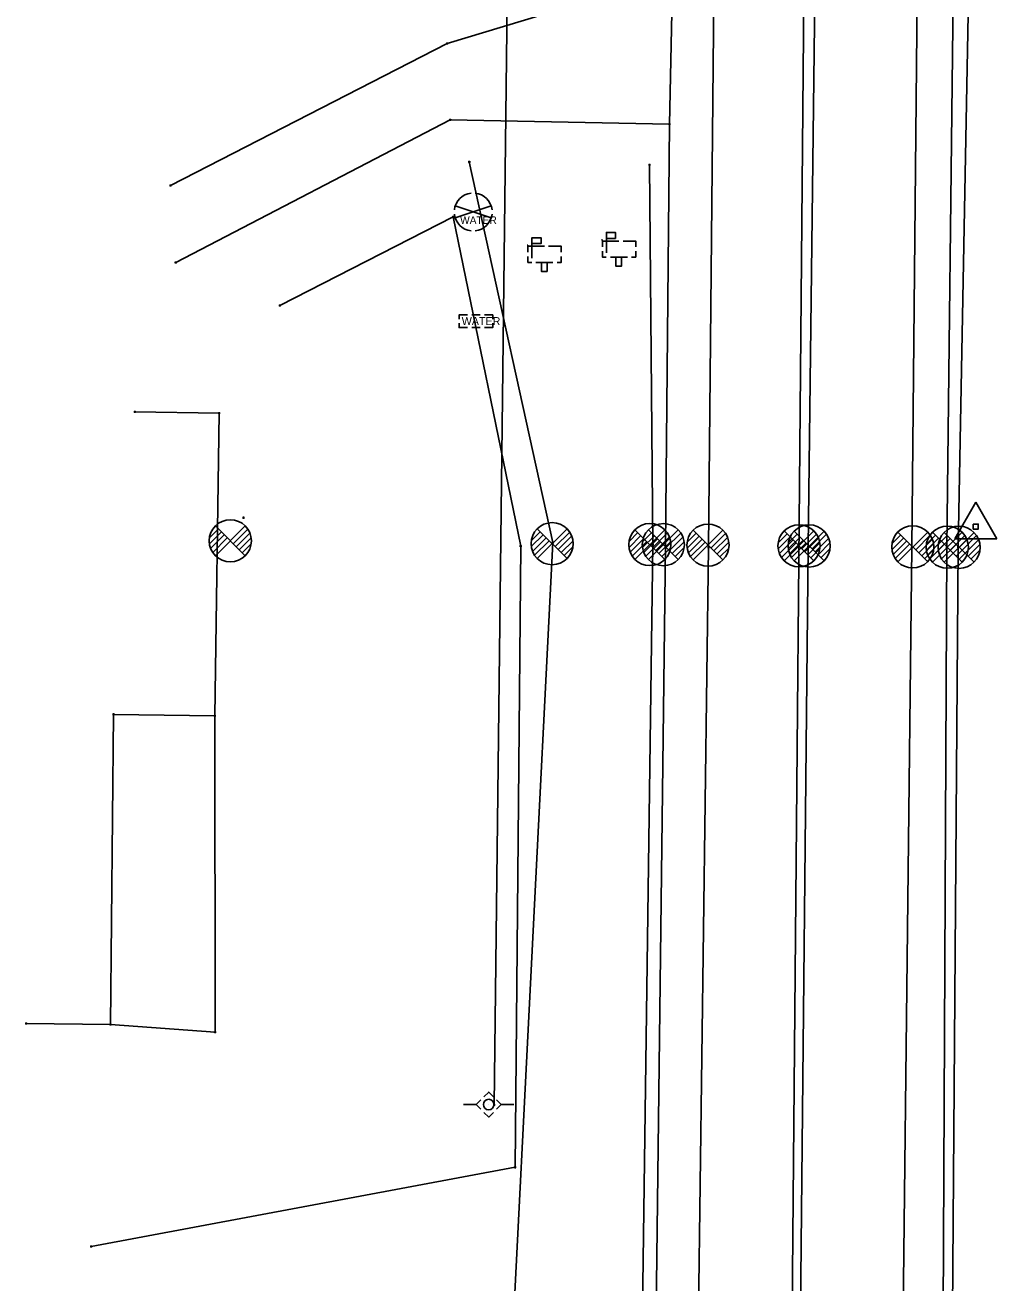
# Model space of a CAD drawing. Extents: x 1954856 to 2011933, y 399149 to 426294.
# Drawn here: x 2003853.9 to 2003969.2, y 411391.5 to 411540.8 of the extents above; entities that cross this region are included whole.
import ezdxf

# ---------------------------------------------------------------- set-up
doc = ezdxf.new("R2010")
doc.units = 0
for name, color, linetype in [('BankMent_ep', 7, 'Continuous'), ('BaselineSurvey', 7, 'Continuous'), ('Building_ep', 7, 'Continuous'), ('Deck_ep', 7, 'Continuous'), ('Driveway_ep', 7, 'Continuous'), ('ElecAer_ep', 7, 'Continuous'), ('Mailbox_ep', 7, 'Continuous'), ('MeterWater_ep', 7, 'Continuous'), ('MonumentNL_ep', 7, 'Continuous'), ('PavtAsphalt_ep', 7, 'Continuous'), ('PavtAsphaltCrown_ep', 7, 'Continuous'), ('PointLocator_ep', 7, 'Continuous'), ('PoleShared_ep', 7, 'Continuous'), ('ShldrPaved_ep', 7, 'Continuous'), ('TreeLineWoods_ep', 7, 'Continuous'), ('ValveCvrWater_ep', 7, 'Continuous'), ('XSPt_ep', 7, 'Continuous')]:
    doc.layers.add(name, color=color, linetype=linetype)

msp = doc.modelspace()

# ---------------------------------------------------------------- linework, layer by layer
at = {"layer": 'BankMent_ep'}
for p, q in [((2003964.59, 411478.82), (2003966.14, 411562.47)), ((2003963.86, 411378.27), (2003964.59, 411478.82))]:
    msp.add_line(p, q, dxfattribs=at)
for points in [[(2003912.38, 411279.6), (2003911.48, 411380.96), (2003916.5, 411479.37), (2003906.57, 411524.55)], [(2003926.31, 411279.68), (2003927.01, 411379.57), (2003928.36, 411479.13), (2003927.97, 411524.18)]]:
    msp.add_lwpolyline(points, dxfattribs=at)
at = {"layer": 'BaselineSurvey'}
msp.add_line((2003939.73, 410808.61), (2003953.03, 412299.6), dxfattribs=at)
msp.add_line((2003939.73, 410808.61), (2003953.03, 412299.6), dxfattribs=at)
at = {"layer": 'Building_ep'}
msp.add_lwpolyline([(2003866.89, 411494.87), (2003876.89, 411494.72), (2003876.35, 411458.79), (2003864.35, 411458.97), (2003863.98, 411422.19), (2003853.98, 411422.29)], dxfattribs=at)
at = {"layer": 'Deck_ep'}
msp.add_lwpolyline([(2003876.35, 411458.79), (2003876.39, 411421.28), (2003863.98, 411422.19)], dxfattribs=at)
at = {"layer": 'Driveway_ep'}
for points in [[(2003871.11, 411521.73), (2003903.94, 411538.58), (2003930.69, 411546.69)], [(2003930.33, 411529), (2003904.31, 411529.53), (2003871.73, 411512.61)]]:
    msp.add_lwpolyline(points, dxfattribs=at)
at = {"layer": 'ElecAer_ep'}
msp.add_lwpolyline([(2003909.52, 411412.64), (2003912.81, 411691.22), (2003877.86, 411706.6)], dxfattribs=at)
at = {"layer": 'Mailbox_ep'}
for p, q in [((2003913.53, 411514.52), (2003913.53, 411513.82)), ((2003915.48, 411514.52), (2003913.53, 411514.52)), ((2003914, 411513.11), (2003914, 411514.84)), ((2003914, 411514.84), (2003914.98, 411514.84)), ((2003917.48, 411514.52), (2003917.48, 411513.82)), ((2003922.37, 411515.14), (2003922.37, 411514.44)), ((2003924.33, 411515.14), (2003922.37, 411515.14)), ((2003922.84, 411513.73), (2003922.84, 411515.46)), ((2003922.84, 411515.46), (2003923.83, 411515.46)), ((2003926.33, 411515.14), (2003926.33, 411514.44)), ((2003917.48, 411513.32), (2003917.48, 411512.61)), ((2003923.33, 411513.23), (2003923.83, 411513.23)), ((2003923.83, 411513.23), (2003925.33, 411513.23)), ((2003926.33, 411513.94), (2003926.33, 411513.23)), ((2003914.48, 411512.61), (2003914.98, 411512.61)), ((2003914.98, 411512.61), (2003916.48, 411512.61)), ((2003915.47, 411511.53), (2003915.47, 411511.53)), ((2003924.31, 411512.16), (2003924.31, 411512.16))]:
    msp.add_line(p, q, dxfattribs=at)
for points in [[(2003923.83, 411516.16), (2003922.84, 411516.16), (2003922.84, 411515.46)], [(2003923.83, 411515.46), (2003923.92, 411515.46), (2003923.92, 411516.16), (2003923.83, 411516.16)], [(2003913.42, 411514.65), (2003913.5, 411514.65), (2003913.53, 411514.48)], [(2003914.98, 411515.53), (2003914, 411515.53), (2003914, 411514.84)], [(2003914.98, 411514.84), (2003915.08, 411514.84), (2003915.08, 411515.53), (2003914.98, 411515.53)], [(2003917.48, 411514.07), (2003917.48, 411514.52), (2003915.98, 411514.52)], [(2003922.26, 411515.27), (2003922.34, 411515.27), (2003922.37, 411515.1)], [(2003926.33, 411514.69), (2003926.33, 411515.14), (2003924.83, 411515.14)], [(2003913.53, 411513.32), (2003913.53, 411512.61), (2003913.98, 411512.61)], [(2003916.98, 411512.61), (2003917.48, 411512.61), (2003917.48, 411513.07)], [(2003922.37, 411513.94), (2003922.37, 411513.23), (2003922.83, 411513.23)], [(2003923.96, 411513.23), (2003923.96, 411512.16), (2003924.65, 411512.16), (2003924.65, 411513.23)], [(2003925.83, 411513.23), (2003926.33, 411513.23), (2003926.33, 411513.69)], [(2003915.12, 411512.61), (2003915.12, 411511.53), (2003915.81, 411511.53), (2003915.81, 411512.61)]]:
    msp.add_lwpolyline(points, dxfattribs=at)
at = {"layer": 'MeterWater_ep'}
msp.add_line((2003907.36, 411505.63), (2003907.36, 411505.63), dxfattribs=at)
for points in [[(2003905.36, 411505.88), (2003905.36, 411506.38), (2003906.36, 411506.38)], [(2003906.86, 411506.38), (2003907.86, 411506.38)], [(2003908.36, 411506.38), (2003909.36, 411506.38), (2003909.36, 411505.88)], [(2003906.36, 411504.88), (2003905.36, 411504.88), (2003905.36, 411505.38)], [(2003907.86, 411504.88), (2003906.86, 411504.88)], [(2003909.36, 411505.38), (2003909.36, 411504.88), (2003908.36, 411504.88)]]:
    msp.add_lwpolyline(points, dxfattribs=at)
at = {"layer": 'MonumentNL_ep'}
for p, q in [((2003964.18, 411479.82), (2003966.68, 411484.15)), ((2003966.68, 411484.15), (2003969.18, 411479.82)), ((2003966.68, 411481.26), (2003966.68, 411481.26)), ((2003964.18, 411479.82), (2003969.18, 411479.82))]:
    msp.add_line(p, q, dxfattribs=at)
msp.add_lwpolyline([(2003966.38, 411481.56), (2003966.98, 411481.56), (2003966.98, 411480.96), (2003966.38, 411480.96)], close=True, dxfattribs=at)
at = {"layer": 'PavtAsphalt_ep'}
for p, q in [((2003934.97, 411478.76), (2003935.91, 411579.3)), ((2003959.08, 411478.78), (2003960.06, 411578.43)), ((2003933.66, 411379.39), (2003934.97, 411478.76)), ((2003957.96, 411378.28), (2003959.08, 411478.78))]:
    msp.add_line(p, q, dxfattribs=at)
at = {"layer": 'PavtAsphaltCrown_ep'}
for p, q in [((2003946.8, 411478.86), (2003947.97, 411578.87)), ((2003945.8, 411378.98), (2003946.8, 411478.86))]:
    msp.add_line(p, q, dxfattribs=at)
at = {"layer": 'PointLocator_ep'}
for p, q in [((2003904.07, 411538.58), (2003903.82, 411538.58)), ((2003903.94, 411538.46), (2003903.94, 411538.71)), ((2003903.94, 411538.58), (2003903.94, 411538.58)), ((2003904.44, 411529.53), (2003904.19, 411529.53)), ((2003904.31, 411529.41), (2003904.31, 411529.66)), ((2003904.31, 411529.53), (2003904.31, 411529.53)), ((2003930.46, 411529), (2003930.21, 411529)), ((2003930.33, 411528.88), (2003930.33, 411529.13)), ((2003930.33, 411529), (2003930.33, 411529)), ((2003906.7, 411524.55), (2003906.45, 411524.55)), ((2003906.57, 411524.42), (2003906.57, 411524.67)), ((2003906.57, 411524.55), (2003906.57, 411524.55)), ((2003928.09, 411524.18), (2003927.84, 411524.18)), ((2003927.97, 411524.06), (2003927.97, 411524.31)), ((2003927.97, 411524.18), (2003927.97, 411524.18)), ((2003871.11, 411521.6), (2003871.11, 411521.85)), ((2003871.23, 411521.73), (2003870.98, 411521.73)), ((2003871.11, 411521.73), (2003871.11, 411521.73)), ((2003904.77, 411518.01), (2003904.52, 411518.01)), ((2003904.64, 411517.88), (2003904.64, 411518.13)), ((2003904.64, 411518.01), (2003904.64, 411518.01)), ((2003871.85, 411512.61), (2003871.6, 411512.61)), ((2003871.73, 411512.48), (2003871.73, 411512.73)), ((2003871.73, 411512.61), (2003871.73, 411512.61)), ((2003884.2, 411507.49), (2003883.95, 411507.49)), ((2003884.07, 411507.37), (2003884.07, 411507.62)), ((2003884.07, 411507.49), (2003884.07, 411507.49)), ((2003866.89, 411494.75), (2003866.89, 411495)), ((2003867.01, 411494.87), (2003866.76, 411494.87)), ((2003866.89, 411494.87), (2003866.89, 411494.87)), ((2003877.01, 411494.72), (2003876.76, 411494.72)), ((2003876.89, 411494.6), (2003876.89, 411494.85)), ((2003876.89, 411494.72), (2003876.89, 411494.72)), ((2003879.9, 411482.31), (2003879.65, 411482.31)), ((2003879.78, 411482.19), (2003879.78, 411482.44)), ((2003879.78, 411482.31), (2003879.78, 411482.31)), ((2003912.79, 411478.95), (2003912.54, 411478.95)), ((2003912.67, 411478.82), (2003912.67, 411479.07)), ((2003912.67, 411478.95), (2003912.67, 411478.95)), ((2003916.62, 411479.37), (2003916.37, 411479.37)), ((2003916.5, 411479.24), (2003916.5, 411479.49)), ((2003916.5, 411479.37), (2003916.5, 411479.37)), ((2003928.49, 411479.13), (2003928.24, 411479.13)), ((2003928.36, 411479), (2003928.36, 411479.25)), ((2003928.36, 411479.13), (2003928.36, 411479.13)), ((2003929.98, 411478.97), (2003929.73, 411478.97)), ((2003929.85, 411478.84), (2003929.85, 411479.09)), ((2003929.85, 411478.97), (2003929.85, 411478.97)), ((2003935.09, 411478.76), (2003934.84, 411478.76)), ((2003934.97, 411478.64), (2003934.97, 411478.89)), ((2003934.97, 411478.76), (2003934.97, 411478.76)), ((2003946.93, 411478.86), (2003946.68, 411478.86)), ((2003946.8, 411478.74), (2003946.8, 411478.99)), ((2003946.8, 411478.86), (2003946.8, 411478.86)), ((2003959.21, 411478.78), (2003958.96, 411478.78)), ((2003959.08, 411478.65), (2003959.08, 411478.9)), ((2003959.08, 411478.78), (2003959.08, 411478.78)), ((2003963.36, 411478.8), (2003963.11, 411478.8)), ((2003963.23, 411478.68), (2003963.23, 411478.93)), ((2003963.23, 411478.8), (2003963.23, 411478.8)), ((2003964.72, 411478.82), (2003964.47, 411478.82)), ((2003964.59, 411478.69), (2003964.59, 411478.94)), ((2003964.59, 411478.82), (2003964.59, 411478.82)), ((2003864.48, 411458.97), (2003864.23, 411458.97)), ((2003864.35, 411458.85), (2003864.35, 411459.1)), ((2003864.35, 411458.97), (2003864.35, 411458.97)), ((2003876.48, 411458.79), (2003876.23, 411458.79)), ((2003876.35, 411458.67), (2003876.35, 411458.92)), ((2003876.35, 411458.79), (2003876.35, 411458.79)), ((2003854.11, 411422.29), (2003853.86, 411422.29)), ((2003853.98, 411422.17), (2003853.98, 411422.42)), ((2003853.98, 411422.29), (2003853.98, 411422.29)), ((2003864.1, 411422.19), (2003863.85, 411422.19)), ((2003863.98, 411422.07), (2003863.98, 411422.32)), ((2003863.98, 411422.19), (2003863.98, 411422.19)), ((2003876.51, 411421.28), (2003876.26, 411421.28)), ((2003876.39, 411421.15), (2003876.39, 411421.4)), ((2003876.39, 411421.28), (2003876.39, 411421.28)), ((2003909.64, 411412.64), (2003909.39, 411412.64)), ((2003909.52, 411412.51), (2003909.52, 411412.76)), ((2003909.52, 411412.64), (2003909.52, 411412.64)), ((2003912.13, 411405.23), (2003911.88, 411405.23)), ((2003912, 411405.1), (2003912, 411405.35)), ((2003912, 411405.23), (2003912, 411405.23)), ((2003861.82, 411395.83), (2003861.57, 411395.83)), ((2003861.7, 411395.7), (2003861.7, 411395.95)), ((2003861.7, 411395.83), (2003861.7, 411395.83))]:
    msp.add_line(p, q, dxfattribs=at)
at = {"layer": 'PoleShared_ep'}
for p, q in [((2003907.38, 411412.67), (2003907.94, 411413.24)), ((2003905.88, 411412.67), (2003907.38, 411412.67)), ((2003907.94, 411412.11), (2003907.38, 411412.67)), ((2003908.87, 411412.67), (2003908.87, 411412.67)), ((2003911.85, 411412.67), (2003910.35, 411412.67))]:
    msp.add_line(p, q, dxfattribs=at)
for points in [[(2003908.3, 411413.6), (2003908.87, 411414.16), (2003909.43, 411413.59)], [(2003909.79, 411413.24), (2003910.35, 411412.67), (2003909.79, 411412.11)], [(2003909.43, 411411.75), (2003908.87, 411411.18), (2003908.3, 411411.75)]]:
    msp.add_lwpolyline(points, dxfattribs=at)
for start, end in [(90, 270), (270, 90)]:
    msp.add_arc((2003908.87, 411412.67), 0.625, start, end, dxfattribs=at)
at = {"layer": 'ShldrPaved_ep'}
for p, q in [((2003963.23, 411478.8), (2003964.4, 411578.36)), ((2003930.33, 411529), (2003930.69, 411546.69)), ((2003929.85, 411478.97), (2003930.33, 411529)), ((2003928.66, 411379.34), (2003929.85, 411478.97)), ((2003962.77, 411378.34), (2003963.23, 411478.8))]:
    msp.add_line(p, q, dxfattribs=at)
at = {"layer": 'TreeLineWoods_ep'}
msp.add_lwpolyline([(2003861.7, 411395.83), (2003912, 411405.23), (2003912.67, 411478.95), (2003904.64, 411518.01), (2003884.07, 411507.49)], dxfattribs=at)
at = {"layer": 'ValveCvrWater_ep'}
for p, q in [((2003904.9, 411517.88), (2003909.17, 411519.3)), ((2003909.17, 411517.88), (2003904.9, 411519.3)), ((2003907.03, 411518.59), (2003907.03, 411518.59))]:
    msp.add_line(p, q, dxfattribs=at)
for start, end in [(96.3794, 173.6206), (6.3794, 83.6206), (186.3794, 263.6206), (276.3794, 353.6206)]:
    msp.add_arc((2003907.03, 411518.59), 2.25, start, end, dxfattribs=at)
at = {"layer": 'XSPt_ep'}
for p, q in [((2003875.73, 411479.92), (2003876.79, 411480.98)), ((2003875.73, 411479.22), (2003877.14, 411480.63)), ((2003875.87, 411478.66), (2003877.49, 411480.28)), ((2003876.43, 411477.8), (2003879.97, 411481.34)), ((2003879.97, 411477.8), (2003876.43, 411481.34)), ((2003878.56, 411479.22), (2003880.29, 411480.95)), ((2003878.91, 411478.86), (2003880.53, 411480.48)), ((2003913.93, 411479.58), (2003914.99, 411480.64)), ((2003913.93, 411478.88), (2003915.34, 411480.29)), ((2003914.63, 411477.46), (2003918.17, 411481)), ((2003918.17, 411477.46), (2003914.63, 411481)), ((2003916.75, 411478.88), (2003918.49, 411480.61)), ((2003917.11, 411478.52), (2003918.73, 411480.14)), ((2003925.53, 411479.48), (2003926.59, 411480.54)), ((2003925.53, 411478.77), (2003926.94, 411480.19)), ((2003926.23, 411477.36), (2003929.77, 411480.89)), ((2003929.77, 411477.36), (2003926.23, 411480.89)), ((2003927.13, 411479.46), (2003928.19, 411480.53)), ((2003927.13, 411478.76), (2003928.54, 411480.17)), ((2003927.83, 411477.34), (2003931.37, 411480.88)), ((2003931.37, 411477.34), (2003927.83, 411480.88)), ((2003928.35, 411478.77), (2003930.09, 411480.5)), ((2003929.95, 411478.76), (2003931.69, 411480.49)), ((2003932.43, 411479.42), (2003933.49, 411480.48)), ((2003932.43, 411478.71), (2003933.84, 411480.12)), ((2003933.13, 411477.3), (2003936.67, 411480.83)), ((2003936.67, 411477.3), (2003933.13, 411480.83)), ((2003935.25, 411478.71), (2003936.99, 411480.44)), ((2003943.23, 411479.32), (2003944.29, 411480.38)), ((2003943.93, 411477.2), (2003947.47, 411480.74)), ((2003947.47, 411477.2), (2003943.93, 411480.74)), ((2003944.42, 411479.31), (2003945.48, 411480.37)), ((2003945.13, 411477.19), (2003948.67, 411480.72)), ((2003948.67, 411477.19), (2003945.13, 411480.72)), ((2003946.05, 411478.61), (2003947.79, 411480.35)), ((2003947.25, 411478.6), (2003948.98, 411480.34)), ((2003956.72, 411479.2), (2003957.78, 411480.26)), ((2003957.43, 411477.08), (2003960.97, 411480.61)), ((2003960.97, 411477.08), (2003957.43, 411480.61)), ((2003959.55, 411478.49), (2003961.28, 411480.23)), ((2003960.82, 411479.16), (2003961.88, 411480.23)), ((2003961.53, 411477.04), (2003965.07, 411480.58)), ((2003965.07, 411477.04), (2003961.53, 411480.58)), ((2003962.22, 411479.15), (2003963.28, 411480.21)), ((2003962.93, 411477.03), (2003966.47, 411480.57)), ((2003966.47, 411477.03), (2003962.93, 411480.57)), ((2003963.65, 411478.46), (2003965.38, 411480.19)), ((2003965.05, 411478.44), (2003966.78, 411480.18)), ((2003876.12, 411478.19), (2003877.85, 411479.92)), ((2003878.2, 411479.57), (2003878.2, 411479.57)), ((2003879.26, 411478.51), (2003880.68, 411479.92)), ((2003879.62, 411478.15), (2003880.68, 411479.22)), ((2003914.07, 411478.32), (2003915.69, 411479.94)), ((2003914.32, 411477.85), (2003916.05, 411479.58)), ((2003916.4, 411479.23), (2003916.4, 411479.23)), ((2003917.46, 411478.17), (2003918.88, 411479.58)), ((2003917.82, 411477.81), (2003918.88, 411478.88)), ((2003925.67, 411478.21), (2003927.29, 411479.83)), ((2003925.91, 411477.75), (2003927.65, 411479.48)), ((2003927.27, 411478.2), (2003928.89, 411479.82)), ((2003927.51, 411477.73), (2003929.25, 411479.46)), ((2003928, 411479.12), (2003928, 411479.12)), ((2003928.71, 411478.42), (2003930.33, 411480.04)), ((2003929.06, 411478.06), (2003930.47, 411479.48)), ((2003929.41, 411477.71), (2003930.47, 411478.77)), ((2003929.6, 411479.11), (2003929.6, 411479.11)), ((2003930.31, 411478.4), (2003931.93, 411480.02)), ((2003930.66, 411478.05), (2003932.07, 411479.46)), ((2003931.01, 411477.7), (2003932.07, 411478.76)), ((2003932.57, 411478.15), (2003934.19, 411479.77)), ((2003932.81, 411477.69), (2003934.55, 411479.42)), ((2003934.9, 411479.06), (2003934.9, 411479.06)), ((2003935.61, 411478.36), (2003937.23, 411479.98)), ((2003935.96, 411478), (2003937.37, 411479.42)), ((2003936.31, 411477.65), (2003937.37, 411478.71)), ((2003943.23, 411478.61), (2003944.64, 411480.03)), ((2003943.37, 411478.05), (2003944.99, 411479.68)), ((2003943.61, 411477.59), (2003945.35, 411479.32)), ((2003944.42, 411478.6), (2003945.84, 411480.02)), ((2003944.57, 411478.04), (2003946.19, 411479.66)), ((2003944.81, 411477.58), (2003946.55, 411479.31)), ((2003945.7, 411478.97), (2003945.7, 411478.97)), ((2003946.41, 411478.26), (2003948.03, 411479.88)), ((2003946.76, 411477.91), (2003948.17, 411479.32)), ((2003946.9, 411478.96), (2003946.9, 411478.96)), ((2003947.11, 411477.55), (2003948.17, 411478.61)), ((2003947.61, 411478.25), (2003949.23, 411479.87)), ((2003947.96, 411477.9), (2003949.37, 411479.31)), ((2003948.31, 411477.54), (2003949.37, 411478.6)), ((2003956.72, 411478.49), (2003958.14, 411479.91)), ((2003956.87, 411477.93), (2003958.49, 411479.55)), ((2003957.11, 411477.47), (2003958.85, 411479.2)), ((2003959.2, 411478.85), (2003959.2, 411478.85)), ((2003959.91, 411478.14), (2003961.53, 411479.76)), ((2003960.26, 411477.79), (2003961.67, 411479.2)), ((2003960.82, 411478.46), (2003962.24, 411479.87)), ((2003960.97, 411477.9), (2003962.59, 411479.52)), ((2003961.21, 411477.43), (2003962.95, 411479.16)), ((2003962.22, 411478.44), (2003963.64, 411479.86)), ((2003962.37, 411477.88), (2003963.99, 411479.51)), ((2003962.61, 411477.42), (2003964.35, 411479.15)), ((2003963.3, 411478.81), (2003963.3, 411478.81)), ((2003964.01, 411478.1), (2003965.63, 411479.72)), ((2003964.36, 411477.75), (2003965.77, 411479.16)), ((2003964.7, 411478.8), (2003964.7, 411478.8)), ((2003965.41, 411478.09), (2003967.03, 411479.71)), ((2003965.76, 411477.74), (2003967.17, 411479.15)), ((2003960.61, 411477.43), (2003961.67, 411478.49)), ((2003964.71, 411477.4), (2003965.77, 411478.46)), ((2003966.11, 411477.38), (2003967.17, 411478.44))]:
    msp.add_line(p, q, dxfattribs=at)
for centre in [(2003878.2, 411479.57), (2003916.4, 411479.23), (2003928, 411479.12), (2003929.6, 411479.11), (2003934.9, 411479.06), (2003945.7, 411478.97), (2003946.9, 411478.96), (2003959.2, 411478.85), (2003963.3, 411478.81), (2003964.7, 411478.8)]:
    msp.add_circle(centre, 2.5, dxfattribs=at)

# ---------------------------------------------------------------- texts
at = {"layer": 'MeterWater_ep'}
msp.add_text('WATER', height=0.95, dxfattribs=at).set_placement((2003905.67, 411505.16))
at = {"layer": 'ValveCvrWater_ep'}
msp.add_text('WATER', height=0.9, dxfattribs=at).set_placement((2003905.48, 411517.17))

doc.saveas('drawing.dxf')
